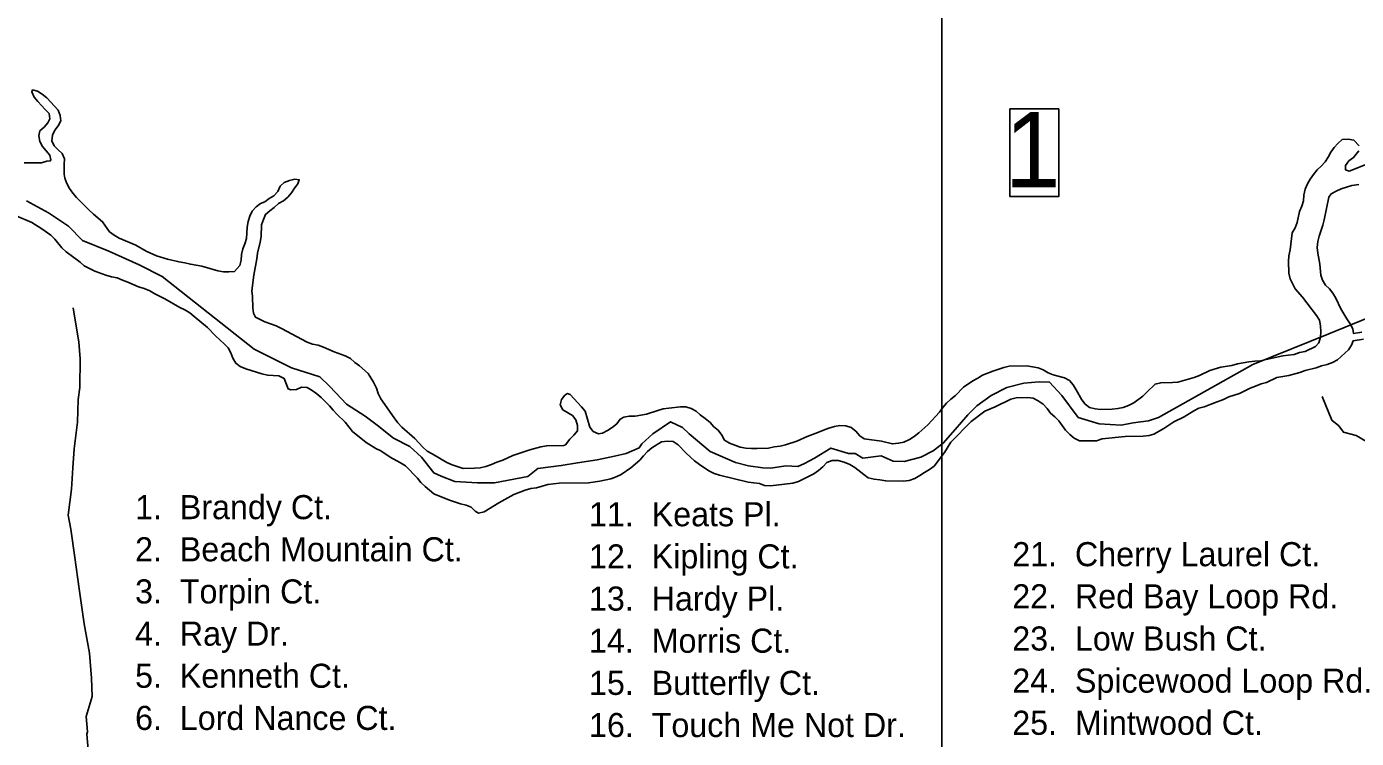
# Model space of a CAD drawing. Extents: x 1945482 to 2853149, y 66427 to 1015778.
# Drawn here: x 2331820 to 2335443, y 186041 to 187980 of the extents above; entities that cross this region are included whole.
import ezdxf

# ---------------------------------------------------------------- set-up
doc = ezdxf.new("R2010")
doc.units = 0
for name, color, linetype in [('Old_Level_11', 7, 'Continuous'), ('Old_Level_31', 7, 'Continuous'), ('Old_Level_35', 7, 'Continuous'), ('Old_Level_48', 7, 'Continuous'), ('Old_Level_49', 7, 'Continuous'), ('Old_Level_60', 7, 'Continuous'), ('Old_Level_63', 7, 'Continuous')]:
    doc.layers.add(name, color=color, linetype=linetype)

msp = doc.modelspace()

# ---------------------------------------------------------------- linework, layer by layer
at = {"layer": 'Old_Level_31'}
msp.add_lwpolyline([(2334498.8, 187755.6), (2334631.8, 187755.6), (2334631.8, 187516.8), (2334498.8, 187516.8)], close=True, dxfattribs=at)
at = {"layer": 'Old_Level_35'}
for points in [[(2331988.8, 186001.1), (2331984.7, 186052.9), (2331986.5, 186059), (2331982.8, 186100.9), (2331998.7, 186155.5), (2331996.7, 186205.5), (2331992, 186273.3), (2331976.8, 186352.7), (2331963.1, 186448.2), (2331951.7, 186533.8), (2331940.6, 186611.4), (2331933.1, 186649.1), (2331942.3, 186719.5), (2331946, 186777.6), (2331949.9, 186829.8), (2331959.1, 186902.2), (2331960.6, 186964.3), (2331965.3, 186996.5), (2331966.2, 187074.5), (2331962.4, 187120.4), (2331946.7, 187213.8)], [(2335811.5, 186651.8), (2335737, 186689.9), (2335663.2, 186734.9), (2335560.8, 186794.9), (2335505.4, 186828.7), (2335441.9, 186866.2), (2335407.5, 186874.9), (2335394.8, 186892.4), (2335376.2, 186907.6), (2335349.6, 186972.6)]]:
    msp.add_lwpolyline(points, dxfattribs=at)
at = {"layer": 'Old_Level_48'}
for points in [[(2331820.2, 187505.5), (2331880.1, 187472.6), (2331934, 187436.7), (2331972.9, 187397.7), (2332044.7, 187367.8), (2332126.7, 187331), (2332190, 187299.5), (2332439.9, 187101.2), (2332541.6, 187050.3), (2332619.5, 187026.3), (2332646.4, 186999.4), (2332691.3, 186951.5), (2332742.2, 186918.5), (2332775.1, 186894.6), (2332820, 186858.6), (2332864.6, 186836.1)], [(2332864.6, 186836.1), (2332895.8, 186807.3), (2332929.5, 186764.6), (2332949.9, 186755.4), (2332986.5, 186740.9), (2333048.6, 186737.3), (2333094.7, 186737.1), (2333186, 186754.8), (2333213.2, 186775.8), (2333276.9, 186784.4), (2333320.6, 186792.1), (2333374.3, 186800.2), (2333421.9, 186810.1), (2333453.6, 186817.4), (2333489, 186832.8), (2333496.5, 186843.7), (2333526.5, 186870.6), (2333574.4, 186903.6), (2333606.9, 186887.5), (2333625.3, 186870.6), (2333682.1, 186822.7), (2333751, 186792.7), (2333786.9, 186783.7), (2333825.8, 186777.8), (2333847.4, 186777), (2333888.7, 186783.7), (2333921.2, 186781.9), (2333939.6, 186789.7), (2333966.5, 186804.7), (2334011.4, 186831.7), (2334059.3, 186816.7), (2334077.3, 186816.7), (2334098.2, 186804.7), (2334148.2, 186810.9), (2334180.8, 186796.2), (2334210.8, 186795.4), (2334256.3, 186807.2), (2334289.7, 186824.5), (2334316.9, 186845.6), (2334349.4, 186882.9), (2334383.8, 186922.3), (2334408.9, 186947.3), (2334447.8, 186974.8), (2334490.9, 186996.6), (2334536.5, 187008.4), (2334578.4, 187012), (2334607.1, 187011.4), (2334640, 186975.4), (2334685, 186915.5), (2334741.8, 186897.6), (2334801.7, 186894.6), (2334834.6, 186900.6), (2334876.5, 186906.5), (2334903.5, 186915.5), (2335160.9, 187059.3), (2335367.5, 187143.2), (2335654.8, 187260)]]:
    msp.add_lwpolyline(points, dxfattribs=at)
at = {"layer": 'Old_Level_49'}
for points in [[(2331820.2, 187505.5), (2331880.1, 187472.6), (2331934, 187436.7), (2331972.9, 187397.7), (2332044.7, 187367.8), (2332126.7, 187331), (2332190, 187299.5), (2332439.9, 187101.2), (2332541.6, 187050.3), (2332619.5, 187026.3), (2332646.4, 186999.4), (2332691.3, 186951.5), (2332742.2, 186918.5), (2332775.1, 186894.6), (2332820, 186858.6), (2332864.6, 186836.1)], [(2332864.6, 186836.1), (2332895.8, 186807.3), (2332929.5, 186764.6), (2332949.9, 186755.4), (2332986.5, 186740.9), (2333048.6, 186737.3), (2333094.7, 186737.1), (2333186, 186754.8), (2333213.2, 186775.8), (2333276.9, 186784.4), (2333320.6, 186792.1), (2333374.3, 186800.2), (2333421.9, 186810.1), (2333453.6, 186817.4), (2333489, 186832.8), (2333496.5, 186843.7), (2333526.5, 186870.6), (2333574.4, 186903.6), (2333606.9, 186887.5), (2333625.3, 186870.6), (2333682.1, 186822.7), (2333751, 186792.7), (2333786.9, 186783.7), (2333825.8, 186777.8), (2333847.4, 186777), (2333888.7, 186783.7), (2333921.2, 186781.9), (2333939.6, 186789.7), (2333966.5, 186804.7), (2334011.4, 186831.7), (2334059.3, 186816.7), (2334077.3, 186816.7), (2334098.2, 186804.7), (2334148.2, 186810.9), (2334180.8, 186796.2), (2334210.8, 186795.4), (2334256.3, 186807.2), (2334289.7, 186824.5), (2334316.9, 186845.6), (2334349.4, 186882.9), (2334383.8, 186922.3), (2334408.9, 186947.3), (2334447.8, 186974.8), (2334490.9, 186996.6), (2334536.5, 187008.4), (2334578.4, 187012), (2334607.1, 187011.4), (2334640, 186975.4), (2334685, 186915.5), (2334741.8, 186897.6), (2334801.7, 186894.6), (2334834.6, 186900.6), (2334876.5, 186906.5), (2334903.5, 186915.5), (2335160.9, 187059.3), (2335367.5, 187143.2), (2335654.8, 187260)]]:
    msp.add_lwpolyline(points, dxfattribs=at)
at = {"layer": 'Old_Level_60'}
for points in [[(2331850.5, 187776.2), (2331841.2, 187788.1), (2331835, 187801.9), (2331836.7, 187807.3), (2331850, 187804), (2331863, 187796), (2331875, 187785.7), (2331906.2, 187752.4), (2331911.5, 187737.9), (2331914, 187722.8), (2331906.5, 187709.7), (2331897.5, 187697.5), (2331890.5, 187684), (2331889, 187669), (2331895.5, 187655.1), (2331906, 187643.9), (2331917.2, 187633.8), (2331923.5, 187620), (2331922.5, 187605), (2331922.7, 187577.8), (2331924.7, 187566.8), (2331929.5, 187552.6), (2331937.2, 187538.7), (2331946.5, 187526.1), (2331956.5, 187514.7), (2331990, 187480.8), (2332002.2, 187469.3), (2332027.2, 187448.3), (2332046.2, 187421.2), (2332058.5, 187411.6), (2332072.7, 187403.8), (2332118.2, 187384.5), (2332146.2, 187368.6), (2332174.2, 187355.4), (2332203.7, 187346), (2332235.5, 187339.1), (2332251, 187336.6), (2332266.5, 187332.6), (2332297.5, 187326.9), (2332341.5, 187314.9), (2332356.5, 187312.3), (2332371.5, 187311.6), (2332386.7, 187312.9), (2332401, 187329), (2332405.2, 187343.5), (2332406, 187359.1), (2332409, 187374.3), (2332414.7, 187388.6), (2332419.2, 187403.1), (2332420.7, 187434), (2332423.5, 187448.9), (2332428.2, 187463.9), (2332435, 187477.4), (2332446, 187488.7)], [(2331813.5, 187608.4), (2331860.7, 187609.1), (2331875.2, 187613.5), (2331884.5, 187613.9), (2331886, 187617.1), (2331883.5, 187630.1), (2331863.7, 187653.6), (2331856.5, 187667), (2331853.7, 187681.9), (2331856.5, 187696), (2331868, 187706.3), (2331878, 187717.7), (2331884, 187728.8), (2331881.5, 187743), (2331870.7, 187753.7), (2331861, 187765.3), (2331850.5, 187776.2)], [(2335345.7, 187148.6), (2335345.2, 187165), (2335342, 187180.5), (2335334, 187193.2), (2335296.2, 187242.5), (2335275.5, 187265.4), (2335262.2, 187293.2), (2335258.5, 187308.7), (2335257.7, 187339.7), (2335259, 187355.8), (2335262, 187371.8), (2335268, 187418.2), (2335275.5, 187431.6), (2335281.5, 187446.1), (2335287.7, 187476.2), (2335294, 187490.5), (2335299, 187505.7), (2335299.5, 187521.1), (2335303.5, 187536.7), (2335309.7, 187551.2), (2335317.2, 187564.2), (2335326, 187577.3), (2335335.5, 187589.4), (2335347, 187599.9), (2335357.5, 187611.9), (2335366.2, 187624.6), (2335373.5, 187638), (2335382.5, 187650.4), (2335392.5, 187661.9), (2335404.2, 187672.5), (2335420, 187673.2), (2335436, 187670.4), (2335450.7, 187655.3)], [(2335449.5, 187641.3), (2335435, 187623.1), (2335422.2, 187614.2), (2335413.2, 187601.3), (2335413, 187589.8), (2335423.2, 187586.1), (2335466.5, 187603.6)], [(2332446, 187488.7), (2332457.5, 187498.4), (2332469.2, 187502.5), (2332481.2, 187511.6), (2332494.2, 187519.3), (2332504.5, 187530.5), (2332511, 187544.8), (2332521.7, 187555.3), (2332536.2, 187560.8), (2332551, 187564.4), (2332563.2, 187562.6), (2332559.5, 187552), (2332549.7, 187539.6), (2332541.5, 187527.1), (2332531.5, 187515.1), (2332520, 187505.4), (2332506.5, 187497.9), (2332494.7, 187487.4), (2332482.5, 187478.4), (2332471, 187468.3), (2332465.2, 187454.3), (2332460.5, 187439.5), (2332459.7, 187407.9), (2332456.7, 187392.8), (2332449.2, 187362.8), (2332447.5, 187347.7), (2332439, 187302.5), (2332433.5, 187259.9), (2332436, 187244.4), (2332436.5, 187214.3), (2332438.7, 187199.4), (2332443.5, 187188.2), (2332469.5, 187175.7), (2332500, 187164.4), (2332514.5, 187157.8), (2332584.5, 187120.7), (2332599.5, 187114.7), (2332614.5, 187111.9), (2332629.5, 187106.3), (2332657.7, 187094.1), (2332688.5, 187083), (2332702.7, 187075.6), (2332714, 187064.7), (2332727.5, 187055.7), (2332750.5, 187035.1), (2332765.2, 187011.5), (2332773.5, 186994.6), (2332778.2, 186980.3), (2332785.2, 186966.4), (2332821.5, 186913.9), (2332831.5, 186900.7), (2332842.5, 186888.6), (2332877.5, 186857.5), (2332899.2, 186834.5), (2332911, 186823.6), (2332925, 186816.2), (2332965.2, 186792.5), (2332980, 186786.1), (2333009.5, 186776.5), (2333040.5, 186776.7), (2333056, 186778.5), (2333071.2, 186781.8), (2333086.5, 186786.7), (2333101.5, 186793.6), (2333117.2, 186799.3), (2333145, 186811.8), (2333191.5, 186827), (2333221, 186834.8), (2333237, 186838), (2333283.5, 186839.2), (2333288, 186841.1), (2333300.2, 186856), (2333311, 186866.9), (2333320.7, 186878.7), (2333320.7, 186893.8), (2333316.5, 186908.6), (2333307, 186920.7), (2333281, 186936.1), (2333273.7, 186949.3), (2333277, 186964), (2333286.5, 186976.3), (2333293.5, 186980.4), (2333301.2, 186978), (2333332.2, 186944.1), (2333341.7, 186932.4), (2333355, 186888.6), (2333364, 186876.6), (2333378, 186870.5), (2333388.7, 186872.6), (2333402.5, 186879.6), (2333415.5, 186888.2), (2333428, 186897.8), (2333437, 186910.4), (2333447, 186916.3), (2333461.7, 186918.6), (2333478.5, 186918.9), (2333509.2, 186924.6)], [(2335457.7, 187147.9), (2335434.5, 187144.3), (2335432.7, 187157.1), (2335426, 187170.6), (2335416.7, 187183.6), (2335400.7, 187211.5), (2335387, 187240), (2335378.7, 187253.5), (2335369, 187265.7), (2335358.5, 187275.4), (2335350.7, 187288.8), (2335346, 187302.5), (2335343.5, 187332.9), (2335337.7, 187363.2), (2335336, 187378.5), (2335338, 187394.2), (2335341.5, 187409.1), (2335351.5, 187438.8), (2335355.2, 187453.5), (2335367.2, 187515.1), (2335374, 187524.2), (2335387.5, 187531.5), (2335401.5, 187538.3), (2335430.5, 187547.1), (2335449.2, 187550)], [(2331791.5, 187464.6), (2331834.7, 187446.5), (2331861.5, 187429.4), (2331886.5, 187412), (2331897, 187400.7), (2331916.7, 187377), (2331927.7, 187366.6), (2331966.2, 187337.8), (2331977.5, 187327.9), (2332006.5, 187313.5), (2332036.2, 187302.5), (2332051.5, 187298.7), (2332066.7, 187296), (2332081.2, 187289.4), (2332096.5, 187284.2), (2332125.2, 187271.1), (2332140.7, 187266.1), (2332156, 187260.1), (2332169.2, 187252.2), (2332197, 187238.7), (2332238, 187214.9), (2332251.5, 187208.2), (2332264.5, 187199.9), (2332277, 187190.5), (2332313.2, 187160.6), (2332334.5, 187137.5), (2332358.2, 187115.6), (2332369, 187104.5), (2332377, 187091.4), (2332382, 187076.5), (2332390, 187063), (2332402.5, 187054), (2332417.2, 187047.3), (2332461.5, 187034.2), (2332476.5, 187030.7), (2332507.2, 187028.2), (2332521.7, 187021.8), (2332532.7, 186993.1), (2332540.5, 186990.1), (2332555.5, 186991.6), (2332569.5, 186998), (2332584.7, 186996.6), (2332598.5, 186989.1), (2332611.2, 186979.5), (2332623, 186969.2), (2332645.5, 186947), (2332655, 186935.1), (2332665.5, 186923.9), (2332688.2, 186902.2), (2332708.2, 186877.4), (2332745, 186846.9), (2332771.2, 186831), (2332785.5, 186824.5), (2332811, 186807.1), (2332839.2, 186791.8), (2332852.5, 186783.3), (2332884.7, 186750), (2332894.5, 186738.3), (2332906, 186727.2), (2332929.2, 186707.2), (2332972.2, 186689.9), (2333002.7, 186680), (2333017.7, 186676.8), (2333031.5, 186670.6), (2333042.5, 186659.6), (2333051.5, 186655), (2333067, 186658.2), (2333106.5, 186682.9), (2333147.5, 186705.3)], [(2333509.2, 186924.6), (2333540, 186934.5), (2333554.7, 186938.4), (2333570, 186940.9), (2333601.2, 186944.1), (2333616.5, 186943.8), (2333631, 186939.7), (2333644.5, 186932.7), (2333655.2, 186922.2), (2333669, 186912.4), (2333682.2, 186901.7), (2333692.5, 186890), (2333704.2, 186880.3), (2333714, 186867.4), (2333721.5, 186853.8), (2333734.7, 186845.1), (2333763.7, 186834.5), (2333779.5, 186831.7), (2333794.5, 186830.6), (2333810.2, 186830.5), (2333841, 186831.8), (2333856.7, 186835.1), (2333873, 186837.2), (2333888, 186840.6), (2333918.7, 186850.6), (2333946.7, 186863.7), (2333975.7, 186874), (2333990.7, 186881.1), (2334005.7, 186886.5), (2334020.7, 186890.5), (2334035.5, 186893.2), (2334052.2, 186892.8), (2334066.7, 186887.8), (2334079.5, 186877.9), (2334090, 186865.5), (2334101.7, 186856.8), (2334149, 186850.7), (2334179, 186843.2), (2334195.5, 186845), (2334210, 186848.2), (2334225, 186855), (2334238, 186863), (2334250.7, 186873.3), (2334275, 186894.9), (2334307.5, 186929.8), (2334316.5, 186942.3), (2334326.5, 186954.4), (2334338.2, 186965.4), (2334350.7, 186974.7), (2334372, 186997.6), (2334398.2, 187014.8), (2334411.5, 187022), (2334424, 187030.4), (2334452.2, 187041.6), (2334482, 187051.2), (2334497, 187054.7), (2334544.7, 187055.9), (2334575.5, 187050.5), (2334589.5, 187044.6), (2334603.2, 187037.2), (2334617, 187031.1), (2334647.2, 187022.8), (2334661, 187016), (2334671.2, 187004), (2334679.5, 186990.9), (2334694.5, 186963.2), (2334704, 186951.5), (2334716, 186942.2), (2334731.2, 186938.8), (2334746.7, 186936.9), (2334777.2, 186937.9), (2334793, 186939.3), (2334807.5, 186942.6), (2334822.2, 186947.6), (2334836, 186955.2), (2334860.7, 186973.1), (2334871.5, 186984.6), (2334894.5, 187006), (2334909.7, 187009.7), (2334941.5, 187010.1), (2334956.5, 187011.4), (2335001.2, 187023.7), (2335015.5, 187029.7), (2335043.5, 187043.1), (2335073.2, 187052.3), (2335103.2, 187057.1), (2335118.7, 187060.9), (2335150, 187066.6), (2335166, 187068.6), (2335181.7, 187069.2), (2335197, 187073.5), (2335242.5, 187082.8), (2335273, 187086.6), (2335287.5, 187092.6), (2335303.2, 187095.3), (2335331.7, 187108.6), (2335340.2, 187118.4), (2335344.5, 187133.6), (2335345.7, 187148.6)], [(2334321, 186819.7), (2334338.2, 186847.6), (2334393, 186904.5), (2334430.7, 186932.8), (2334459, 186944.2), (2334501.2, 186965.2), (2334516, 186968.9), (2334547.5, 186969.4), (2334562.5, 186967.8), (2334576, 186960.8), (2334589.2, 186951.4), (2334600, 186940.1), (2334609.5, 186927.2), (2334621.5, 186917), (2334632.5, 186906.2), (2334650.7, 186880.3), (2334662, 186868.9), (2334674, 186859.1), (2334688, 186851.4), (2334735, 186851.8), (2334750, 186856.9), (2334812.7, 186863.2), (2334862.2, 186864.6), (2334878.2, 186866.4), (2334891.2, 186870.1), (2334918.5, 186885.2), (2334945.2, 186903.7), (2334973.2, 186917.4), (2334999.7, 186933.2), (2335013.2, 186940.2), (2335028.2, 186944.2), (2335056.2, 186955.5), (2335081, 186964.3), (2335095, 186971), (2335124.7, 186980.9), (2335153.2, 186994.6), (2335168.2, 187000.8), (2335183, 187006.4), (2335197.7, 187010.5), (2335226, 187024.4), (2335258.5, 187029.2), (2335288.7, 187037.9), (2335303.5, 187043), (2335333.2, 187050.8), (2335348, 187056), (2335362.7, 187059.7), (2335377.7, 187065.1), (2335391.5, 187072.2), (2335421, 187099.8), (2335429.7, 187112.3), (2335434, 187124.2), (2335462, 187128.3)], [(2333147.5, 186705.3), (2333178.2, 186717.1), (2333193.5, 186721.4), (2333209.2, 186723.5), (2333240, 186732.5), (2333255.5, 186734.9), (2333271.2, 186735.9), (2333351.2, 186736.8), (2333381.5, 186741.8), (2333412, 186748.2), (2333426.5, 186753.4), (2333440.2, 186760), (2333466, 186777.6), (2333490.5, 186798.6), (2333500.5, 186810.8), (2333511.2, 186822.3), (2333523.7, 186832.1), (2333550, 186849.2), (2333566.2, 186851.1), (2333581.5, 186849.6), (2333595.2, 186840.9), (2333616.7, 186818.3), (2333640, 186797.4), (2333653, 186787.1), (2333679, 186769.9), (2333693, 186763), (2333707.5, 186757.7), (2333785.5, 186739.3), (2333816.5, 186735.7), (2333830.7, 186730.1), (2333846, 186729.2), (2333862.2, 186730.5), (2333907.2, 186736), (2333923, 186740.8), (2333964.5, 186761.8), (2333977.5, 186770.7), (2333989.2, 186781.1), (2334000.5, 186792.2), (2334015, 186798.4), (2334031.2, 186798.3), (2334047.2, 186793.4), (2334063, 186786.7), (2334076.5, 186779.4), (2334100.7, 186759.5), (2334113.2, 186750.8), (2334129, 186746.9), (2334144.5, 186745.5), (2334160.5, 186742.6), (2334208.2, 186742), (2334224.2, 186744), (2334239.5, 186749.2), (2334253.5, 186757), (2334266.2, 186765.7), (2334280, 186773.3), (2334292.7, 186783), (2334321, 186819.7)]]:
    msp.add_lwpolyline(points, dxfattribs=at)
at = {"layer": 'Old_Level_63'}
msp.add_lwpolyline([(2334313.2, 192135.8), (2353909.6, 192135.8), (2353909.6, 184193.5), (2334313.2, 184193.5)], close=True, dxfattribs=at)

# ---------------------------------------------------------------- texts
at = {"layer": 'Old_Level_11'}
for s, p in [('1.  Brandy Ct.', (2332115.8, 186638.2)), ('11.  Keats Pl.', (2333352.4, 186618.9)), ('2.  Beach Mountain Ct.', (2332115.8, 186523.4)), ('12.  Kipling Ct.', (2333352.4, 186504)), ('21.  Cherry Laurel Ct.', (2334505.3, 186510.1)), ('3.  Torpin Ct.', (2332115.8, 186408.6)), ('13.  Hardy Pl.', (2333352.4, 186389.2)), ('22.  Red Bay Loop Rd.', (2334505.3, 186395.3)), ('4.  Ray Dr.', (2332115.8, 186293.7)), ('14.  Morris Ct.', (2333352.4, 186274.4)), ('23.  Low Bush Ct.', (2334505.3, 186280.4)), ('5.  Kenneth Ct.', (2332115.8, 186178.9)), ('24.  Spicewood Loop Rd.', (2334505.3, 186165.6)), ('15.  Butterfly Ct.', (2333352.4, 186159.6)), ('6.  Lord Nance Ct.', (2332115.8, 186064.1)), ('16.  Touch Me Not Dr.', (2333352.4, 186044.7)), ('25.  Mintwood Ct.', (2334505.3, 186050.8))]:
    msp.add_text(s, height=65.617, dxfattribs=at).set_placement(p)
at = {"layer": 'Old_Level_31'}
msp.add_text('1', height=205.1, dxfattribs=at).set_placement((2334484.4, 187542.5))

doc.saveas('drawing.dxf')
